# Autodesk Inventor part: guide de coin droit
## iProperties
Shininess: 64.0
Length Units: 11269
Angle Units: 11279
Time Units: 11290
Mass Units: 11283
Length Display Precision: 3
Angle Display Precision: 2
Compacted: True
Part Number: guide de coin droit
Document SubType Name: Modeling
Created: 2004-12
Material: Par défaut
Designer: LEGERET Philippe
Density: 0.0
Volumn: 0.0
Area: 0.0
PropertySet Name: Model Information
Control State: 0
Master: False
Checked Out: False
Author: LEGERET Philippe
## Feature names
1. Extrusion1
2. Extrusion2
3. Perçage2 [Hole]
4. Extrusion5
5. Extrusion7
6. Symétrie3 [Mirror]
7. Extrusion8
